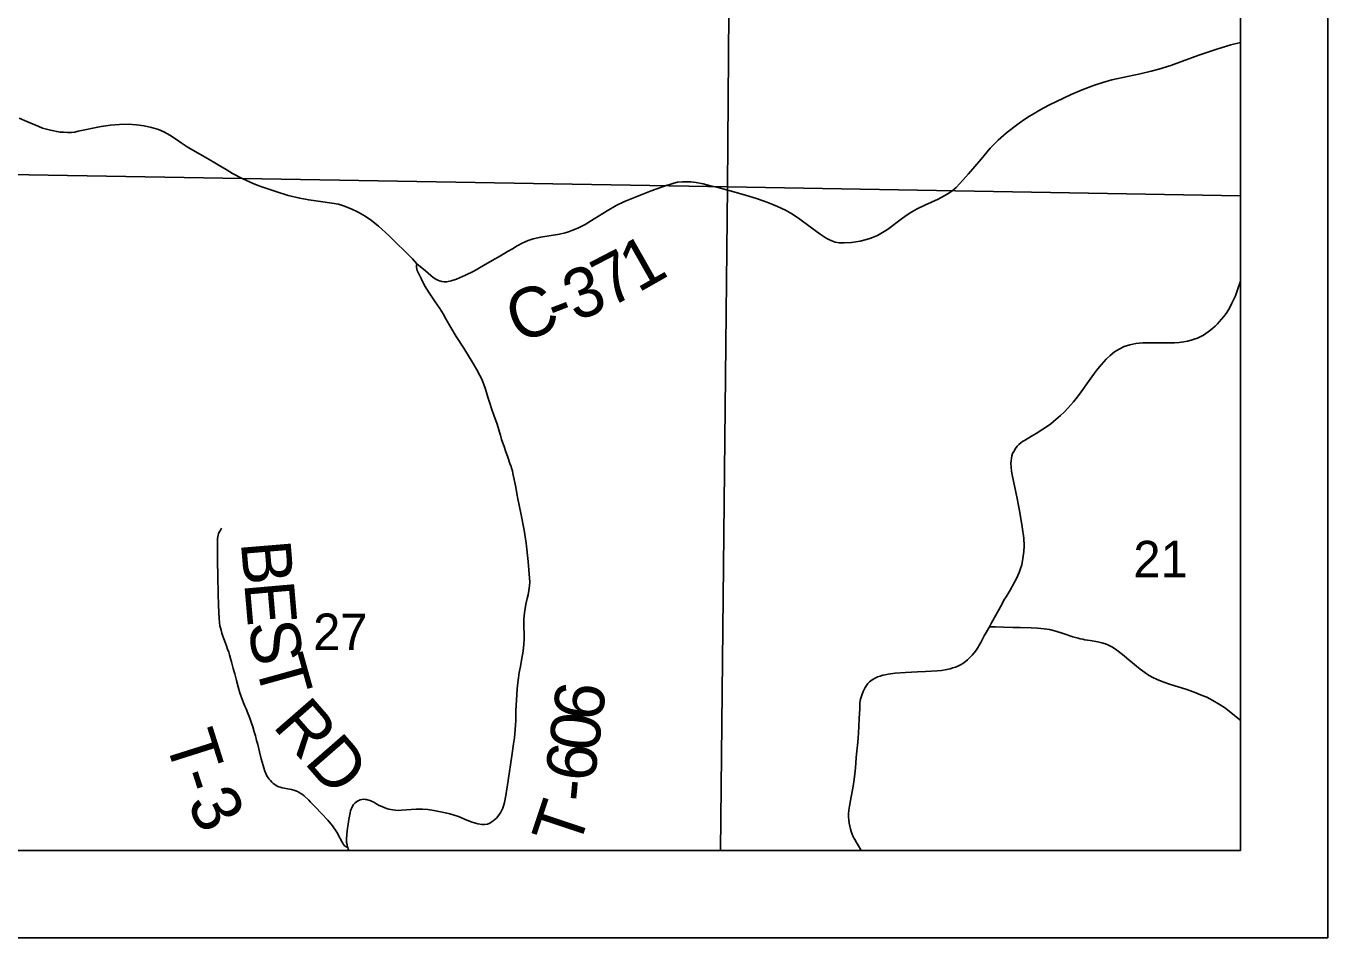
# Model space of a CAD drawing. Extents: x 0 to 34, y 0 to 22.
# Drawn here: x 7.51 to 9, y 14 to 15.043 of the extents above; entities that cross this region are included whole.
import ezdxf

# ---------------------------------------------------------------- set-up
doc = ezdxf.new("R2010")
doc.units = 0
for name, color, linetype in [('GM_X_Corporation', 7, 'Continuous'), ('GM_X_County_Road', 7, 'Continuous'), ('GM_X_County_Road_Text', 7, 'Continuous'), ('GM_X_Section_Text', 7, 'Continuous'), ('GM_X_Township_Road', 7, 'Continuous'), ('GM_X_Township_Road_Text', 7, 'Continuous'), ('GM_X_Township_Text', 7, 'Continuous'), ('SH_Data', 7, 'Continuous')]:
    doc.layers.add(name, color=color, linetype=linetype)

msp = doc.modelspace()

# ---------------------------------------------------------------- linework, layer by layer
at = {"layer": 'GM_X_Corporation'}
msp.add_lwpolyline([(2.1, 19.4241), (2.1, 14.1), (8.9, 14.1), (8.9, 16.8499)], dxfattribs=at)
for points in [[(8.3203, 15.8594), (8.313, 14.8592), (7.3131, 14.8764), (7.3273, 15.8762)], [(8.9, 14.8488), (8.9, 15.8484), (8.3203, 15.8594), (8.313, 14.8592)], [(7.3003, 14.1), (8.305, 14.1), (8.313, 14.8592), (7.3131, 14.8764)], [(8.305, 14.1), (8.9, 14.1), (8.9, 14.8488), (8.313, 14.8592)]]:
    msp.add_lwpolyline(points, close=True, dxfattribs=at)
at = {"layer": 'GM_X_County_Road'}
for points in [[(8.6467, 14.932), (8.6531, 14.9365), (8.6586, 14.9401), (8.6636, 14.9431), (8.6686, 14.946), (8.675, 14.9496), (8.6812, 14.9529), (8.6894, 14.957), (8.6982, 14.9612), (8.7063, 14.9648), (8.7189, 14.9701), (8.7329, 14.9755), (8.7423, 14.9787), (8.7525, 14.9815), (8.7706, 14.9856), (8.7851, 14.9886), (8.7977, 14.9915), (8.8066, 14.9938), (8.8201, 14.9981), (8.8335, 15.003), (8.8522, 15.0098), (8.8728, 15.0167), (8.8889, 15.0215), (8.9, 15.0242)], [(7.5024, 14.9376), (7.5111, 14.9341), (7.5248, 14.9283), (7.5291, 14.9265), (7.5336, 14.9253), (7.538, 14.9242), (7.5419, 14.9231), (7.5452, 14.9225), (7.5492, 14.9219), (7.5531, 14.9217), (7.5574, 14.9214), (7.562, 14.9214), (7.5661, 14.9219), (7.5699, 14.9228), (7.5961, 14.9282), (7.6066, 14.9298), (7.6171, 14.9306), (7.6271, 14.9308), (7.6365, 14.9303), (7.6452, 14.9291), (7.6538, 14.9272), (7.6616, 14.9247), (7.6679, 14.922), (7.6745, 14.9184), (7.6823, 14.9132), (7.6878, 14.9095), (7.6945, 14.9051), (7.6981, 14.9027), (7.7071, 14.8976), (7.7197, 14.8905), (7.7261, 14.8867), (7.732, 14.8832), (7.7392, 14.8789), (7.7463, 14.8745), (7.7573, 14.8687), (7.7708, 14.8626), (7.7788, 14.8594), (7.7958, 14.8537), (7.8101, 14.8494), (7.8233, 14.8462), (7.8336, 14.8443), (7.8471, 14.8424), (7.8601, 14.8407), (7.8675, 14.8393), (7.8735, 14.8375), (7.8823, 14.8341), (7.8902, 14.8304), (7.8983, 14.8257), (7.9056, 14.8207), (7.9133, 14.8144), (7.9253, 14.8035), (7.9523, 14.777), (7.9574, 14.7713)], [(8.5156, 14.8251), (8.5219, 14.8294), (8.53, 14.834), (8.5388, 14.8384), (8.5539, 14.8452), (8.5609, 14.8489), (8.5644, 14.8508), (8.5694, 14.8543), (8.5744, 14.8584), (8.5786, 14.8629), (8.5886, 14.8739), (8.603, 14.891), (8.6135, 14.9033), (8.6227, 14.9126), (8.6321, 14.9209), (8.6404, 14.9275), (8.6467, 14.932)], [(7.9574, 14.7713), (7.9673, 14.7631), (7.9732, 14.7578), (7.9761, 14.7555), (7.9791, 14.7537), (7.982, 14.7522), (7.9859, 14.751), (7.9886, 14.7505), (7.9917, 14.7507), (7.9965, 14.7515), (8.0028, 14.7536), (8.0131, 14.758), (8.0224, 14.7626), (8.0335, 14.7691), (8.0437, 14.775), (8.0532, 14.7803), (8.0612, 14.7851), (8.0668, 14.7884), (8.0722, 14.7917), (8.0777, 14.7947), (8.0846, 14.7977), (8.0906, 14.7998), (8.0991, 14.8018), (8.1206, 14.8052), (8.1272, 14.8067), (8.1308, 14.8078), (8.1348, 14.8091), (8.1416, 14.8121), (8.1498, 14.8163), (8.1604, 14.8226), (8.1751, 14.8318), (8.1854, 14.8377), (8.195, 14.8424), (8.2082, 14.8479), (8.2256, 14.8545), (8.2437, 14.861), (8.2467, 14.8619), (8.2514, 14.8633), (8.2557, 14.8644), (8.2614, 14.8648), (8.2656, 14.8651), (8.2709, 14.8648), (8.2771, 14.864), (8.2851, 14.8625), (8.2935, 14.8605), (8.3008, 14.8587), (8.3157, 14.8546), (8.3336, 14.8496), (8.3462, 14.8458), (8.3591, 14.8413), (8.3701, 14.8368), (8.3791, 14.8324), (8.3872, 14.8278), (8.3955, 14.8222), (8.4075, 14.8133), (8.4189, 14.8049), (8.4256, 14.8006), (8.4287, 14.7989), (8.4322, 14.7973), (8.4361, 14.7959), (8.4409, 14.7951), (8.4463, 14.795), (8.4549, 14.7956), (8.4646, 14.7971), (8.4718, 14.7988), (8.4756, 14.8), (8.4788, 14.8011), (8.4845, 14.8035), (8.4903, 14.8068), (8.4959, 14.8105), (8.5132, 14.8235), (8.5156, 14.8251)], [(8.6126, 14.356), (8.615, 14.3604), (8.6267, 14.3816), (8.6292, 14.3862), (8.6317, 14.3902), (8.6362, 14.398), (8.6413, 14.4069), (8.6434, 14.4111), (8.6451, 14.4147), (8.6465, 14.4179), (8.6478, 14.4215), (8.6495, 14.4268), (8.651, 14.434), (8.652, 14.4419), (8.6523, 14.4486), (8.6518, 14.4572), (8.6501, 14.4701), (8.6474, 14.4866), (8.6444, 14.5025), (8.6385, 14.5299), (8.6379, 14.5338), (8.6373, 14.5387), (8.6372, 14.5431), (8.6373, 14.5457), (8.6377, 14.5488), (8.6384, 14.5515), (8.6391, 14.5541), (8.6404, 14.5566), (8.6423, 14.5598), (8.6443, 14.5624), (8.6463, 14.5645), (8.6485, 14.5662), (8.6506, 14.5677), (8.6526, 14.5691), (8.6607, 14.574), (8.6661, 14.5772), (8.6792, 14.5855), (8.6827, 14.588), (8.686, 14.5907), (8.6939, 14.5976), (8.6981, 14.6015), (8.7026, 14.6064), (8.7088, 14.6133), (8.7119, 14.6172), (8.7156, 14.6221), (8.7278, 14.6393), (8.7348, 14.6489), (8.7407, 14.6561), (8.7462, 14.6621), (8.7508, 14.6664), (8.7558, 14.6703), (8.7612, 14.6736), (8.7668, 14.6764), (8.7734, 14.6786), (8.7768, 14.6793), (8.7802, 14.68), (8.7838, 14.6805), (8.7883, 14.6808), (8.8033, 14.6808), (8.8194, 14.6806), (8.8243, 14.6808), (8.8299, 14.6813), (8.835, 14.6819), (8.8393, 14.6827), (8.8435, 14.6838), (8.8468, 14.6848), (8.8508, 14.6862), (8.8545, 14.688), (8.8576, 14.6897), (8.8604, 14.6916), (8.863, 14.6934), (8.8658, 14.6955), (8.8683, 14.6974), (8.8709, 14.7), (8.8734, 14.7023), (8.8756, 14.7049), (8.8808, 14.7109), (8.8834, 14.7144), (8.886, 14.7185), (8.8881, 14.7221), (8.8901, 14.7261), (8.8919, 14.7298), (8.894, 14.7344), (8.8965, 14.7414), (8.8994, 14.7501), (8.9, 14.752)], [(8.4661, 14.1), (8.4656, 14.1007), (8.4626, 14.1055), (8.4603, 14.1091), (8.4585, 14.1125), (8.4568, 14.1158), (8.4555, 14.1188), (8.4544, 14.1217), (8.4536, 14.1245), (8.4527, 14.1277), (8.452, 14.1312), (8.4515, 14.1346), (8.4513, 14.1386), (8.4514, 14.1415), (8.4518, 14.146), (8.4524, 14.1509), (8.4536, 14.1573), (8.4565, 14.1735), (8.4579, 14.1814), (8.4586, 14.1876), (8.4592, 14.1944), (8.4602, 14.2061), (8.461, 14.2139), (8.4615, 14.2203), (8.4622, 14.2284), (8.4628, 14.2345), (8.4632, 14.2413), (8.4636, 14.2512), (8.4641, 14.2617), (8.4643, 14.2684), (8.4647, 14.2716), (8.4654, 14.2743), (8.4664, 14.2778), (8.468, 14.2818), (8.4691, 14.2841), (8.4702, 14.2864), (8.4718, 14.2888), (8.4735, 14.2911), (8.4752, 14.2928), (8.4768, 14.2941), (8.4794, 14.296), (8.4819, 14.2973), (8.4845, 14.2986), (8.4875, 14.2996), (8.4906, 14.3005), (8.4933, 14.3011), (8.4968, 14.3017), (8.5049, 14.3028), (8.5167, 14.3036), (8.5302, 14.3042), (8.5396, 14.3048), (8.5526, 14.3055), (8.5576, 14.306), (8.5618, 14.3067), (8.5678, 14.308), (8.5708, 14.3088), (8.5736, 14.3099), (8.5764, 14.3109), (8.5793, 14.3123), (8.5823, 14.3141), (8.5853, 14.3163), (8.5876, 14.3182), (8.5906, 14.3211), (8.5928, 14.3234), (8.595, 14.3262), (8.5976, 14.3297), (8.6027, 14.3381), (8.6067, 14.3454), (8.6126, 14.356)]]:
    msp.add_lwpolyline(points, dxfattribs=at)
at = {"layer": 'GM_X_Township_Road'}
for points in [[(7.8783, 14.1033), (7.8781, 14.1041), (7.8775, 14.1065), (7.8769, 14.109), (7.8768, 14.1115), (7.8769, 14.1139), (7.8777, 14.1225), (7.8794, 14.1353), (7.8801, 14.1393), (7.8805, 14.1413), (7.881, 14.143), (7.8815, 14.1453), (7.8823, 14.1474), (7.8829, 14.1489), (7.8838, 14.1507), (7.885, 14.1525), (7.8864, 14.1541), (7.8888, 14.1561), (7.8909, 14.1573), (7.8925, 14.1578), (7.8944, 14.1583), (7.8962, 14.1586), (7.898, 14.1585), (7.8996, 14.1582), (7.901, 14.1579), (7.9025, 14.1574), (7.9045, 14.1567), (7.9061, 14.156), (7.908, 14.1551), (7.9117, 14.153), (7.9142, 14.1515), (7.9171, 14.1502), (7.9199, 14.1491), (7.9225, 14.1481), (7.9252, 14.1474), (7.9277, 14.1469), (7.93, 14.1465), (7.933, 14.1462), (7.9366, 14.1459), (7.9399, 14.1462), (7.9565, 14.1472), (7.9639, 14.1474), (7.97, 14.1469), (7.9769, 14.1459), (7.9843, 14.1444), (7.9901, 14.143), (7.995, 14.1419), (8.0001, 14.1403), (8.0048, 14.1388), (8.0145, 14.1348), (8.0208, 14.1324), (8.0272, 14.1306), (8.0321, 14.1298), (8.0351, 14.1298), (8.0381, 14.1303), (8.041, 14.1314), (8.0447, 14.1338), (8.0484, 14.137), (8.0513, 14.1403), (8.0536, 14.1439), (8.0556, 14.1485), (8.0576, 14.155), (8.0592, 14.1629), (8.0617, 14.1802), (8.066, 14.2084), (8.068, 14.2219), (8.0689, 14.229), (8.0697, 14.2386), (8.0706, 14.2489), (8.0707, 14.2597), (8.0716, 14.2783), (8.0721, 14.2851), (8.0729, 14.2919), (8.0736, 14.2974), (8.0746, 14.3036), (8.0758, 14.3105), (8.0772, 14.3176), (8.0789, 14.328), (8.0797, 14.336), (8.08, 14.3422), (8.0801, 14.3481), (8.0797, 14.3546), (8.0799, 14.3652), (8.0806, 14.3719), (8.0821, 14.3818), (8.0836, 14.3884), (8.0846, 14.3923), (8.0856, 14.3974), (8.0863, 14.4029), (8.0866, 14.4072), (8.0859, 14.416), (8.0848, 14.4307), (8.0823, 14.4517), (8.08, 14.4664), (8.0763, 14.486), (8.073, 14.5024), (8.0719, 14.5085), (8.0705, 14.5158), (8.0681, 14.528), (8.0673, 14.5314), (8.0666, 14.5342), (8.0658, 14.5372), (8.0652, 14.5393), (8.0638, 14.5428), (8.0614, 14.55), (8.0587, 14.5572), (8.0571, 14.5622), (8.0543, 14.5703), (8.0529, 14.575), (8.0518, 14.5786), (8.0502, 14.5839), (8.0487, 14.5887), (8.0459, 14.5969), (8.0433, 14.6045), (8.0403, 14.613), (8.0385, 14.6185), (8.0369, 14.6239), (8.0354, 14.629), (8.0341, 14.6331), (8.0327, 14.6362), (8.0312, 14.6399), (8.0293, 14.6435), (8.0255, 14.6506), (8.0205, 14.6592), (8.011, 14.6745), (8.0024, 14.6881), (7.9963, 14.6983), (7.9904, 14.7082), (7.9873, 14.7139), (7.9835, 14.72), (7.9784, 14.7278), (7.9715, 14.7381), (7.9662, 14.7465), (7.9625, 14.7535), (7.9592, 14.7603), (7.9578, 14.7635), (7.9572, 14.7654), (7.9569, 14.7673), (7.957, 14.7695), (7.9574, 14.7713)], [(7.8783, 14.1033), (7.8765, 14.1042), (7.8753, 14.105), (7.8743, 14.1057), (7.8733, 14.107), (7.8726, 14.1082), (7.8716, 14.1099), (7.8708, 14.1117), (7.8696, 14.1139), (7.8657, 14.1209), (7.8609, 14.1281), (7.8553, 14.1347), (7.8481, 14.1424), (7.8414, 14.1495), (7.8376, 14.1535), (7.8357, 14.1554), (7.8337, 14.1574), (7.8282, 14.1625), (7.8263, 14.1641), (7.8237, 14.1657), (7.8215, 14.1671), (7.8189, 14.1683), (7.8167, 14.169), (7.814, 14.1696), (7.8031, 14.1718), (7.8008, 14.1726), (7.7984, 14.1734), (7.7965, 14.1742), (7.7947, 14.1755), (7.793, 14.1766), (7.7913, 14.1782), (7.7897, 14.18), (7.7885, 14.1815), (7.7871, 14.1833), (7.7858, 14.1854), (7.7846, 14.1879), (7.7833, 14.1907), (7.7821, 14.1944), (7.7814, 14.1972), (7.7792, 14.205), (7.7774, 14.2129), (7.7752, 14.2213), (7.774, 14.2259), (7.7725, 14.2313), (7.7713, 14.2359), (7.7696, 14.2414), (7.7681, 14.2456), (7.7662, 14.2513), (7.7638, 14.2572), (7.762, 14.2619), (7.7606, 14.2653), (7.7591, 14.269), (7.7563, 14.2763), (7.7547, 14.2805), (7.7528, 14.2874), (7.7508, 14.2945), (7.7489, 14.302), (7.7472, 14.3083), (7.7454, 14.3157), (7.7442, 14.3198), (7.743, 14.3237), (7.742, 14.3267), (7.7407, 14.3302), (7.7393, 14.3343), (7.7365, 14.3421), (7.7354, 14.3453), (7.7342, 14.3486), (7.7332, 14.3522), (7.7325, 14.3547), (7.7319, 14.3571), (7.7313, 14.3609), (7.731, 14.3655), (7.7304, 14.3803), (7.7299, 14.394), (7.7294, 14.4132), (7.7291, 14.4319), (7.729, 14.4455), (7.7291, 14.4539), (7.7291, 14.457), (7.7294, 14.4588), (7.7298, 14.4606), (7.7304, 14.4623), (7.7311, 14.464), (7.7326, 14.4665), (7.7338, 14.4689)], [(8.9, 14.2488), (8.8991, 14.2495), (8.889, 14.2578), (8.8815, 14.2634), (8.8748, 14.2679), (8.8684, 14.2716), (8.8612, 14.2753), (8.8561, 14.2775), (8.8468, 14.2812), (8.8375, 14.2844), (8.8197, 14.29), (8.8109, 14.293), (8.8045, 14.2955), (8.7995, 14.298), (8.7946, 14.3007), (8.7905, 14.3035), (8.7851, 14.3076), (8.7745, 14.3163), (8.7648, 14.3241), (8.7584, 14.329), (8.7533, 14.3325), (8.7489, 14.3349), (8.7455, 14.3364), (8.7414, 14.3377), (8.7365, 14.3388), (8.7279, 14.3401), (8.7218, 14.3411), (8.7194, 14.3416), (8.7164, 14.3423), (8.714, 14.343), (8.7079, 14.3445), (8.6968, 14.3484), (8.6885, 14.3509), (8.6813, 14.3527), (8.6751, 14.3537), (8.6677, 14.3545), (8.6603, 14.3549), (8.6479, 14.3551), (8.6392, 14.3551), (8.6286, 14.3554), (8.6194, 14.3558), (8.6126, 14.356)], [(7.8796, 14.1), (7.8788, 14.1019), (7.8783, 14.1033)]]:
    msp.add_lwpolyline(points, dxfattribs=at)
at = {"layer": 'GM_X_Township_Text'}
msp.add_lwpolyline([(6.4571, 16.891), (6.446, 16.7493), (6.4489, 16.4198), (6.4561, 16.2366), (6.4452, 15.3843), (6.4323, 14.1), (8.9, 14.1), (8.9, 16.8499)], dxfattribs=at)
at = {"layer": 'SH_Data'}
for p, q in [((9, 21), (9, 14)), ((8.9, 20.9), (8.9, 14.1)), ((2.1, 14.1), (8.9, 14.1)), ((2, 14), (9, 14))]:
    msp.add_line(p, q, dxfattribs=at)

# ---------------------------------------------------------------- texts
at = {"layer": 'GM_X_County_Road_Text'}
for s, rotation, p in [('1', 29.5196, (8.2104, 14.7375)), ('7', 27.4691, (8.1774, 14.7203)), ('3', 21.4703, (8.1389, 14.7048)), ('C', 21.0092, (8.0731, 14.6795)), ('-', 21.0715, (8.1167, 14.6962))]:
    msp.add_text(s, height=0.0568, rotation=rotation, dxfattribs=at).set_placement(p)
at = {"layer": 'GM_X_Section_Text'}
for s, p in [('21', (8.7773, 14.4124)), ('27', (7.8386, 14.3292))]:
    msp.add_text(s, height=0.04186, rotation=0, dxfattribs=at).set_placement(p)
at = {"layer": 'GM_X_Township_Road_Text'}
for s, height, rotation, p in [('B', 0.0568, 274.7319, (7.7559, 14.4526)), ('E', 0.0568, 274.976, (7.7597, 14.4059)), ('S', 0.0568, 279.031, (7.7639, 14.3592)), ('T', 0.0568, 285.5435, (7.7715, 14.3144)), ('6', 0.0568, 82.9577, (8.169, 14.2467)), ('RD', 0.05682, 311.0922, (7.7912, 14.2421)), ('0', 0.0568, 82.9438, (8.1647, 14.2119)), ('T', 0.0568, 287.5974, (7.6687, 14.2269)), ('6', 0.0568, 82.8517, (8.1603, 14.1771)), ('-', 0.0568, 288.0595, (7.6817, 14.1859)), ('3', 0.0568, 298.0327, (7.6932, 14.1538)), ('-', 0.0568, 84.5179, (8.1581, 14.1543)), ('T', 0.0568, 71.5325, (8.1418, 14.1003))]:
    msp.add_text(s, height=height, rotation=rotation, dxfattribs=at).set_placement(p)

doc.saveas('drawing.dxf')
